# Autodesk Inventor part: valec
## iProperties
Shininess: 64.0
Length Units: 11269
Angle Units: 11279
Time Units: 11290
Mass Units: 11283
Length Display Precision: 3
Angle Display Precision: 2
Compacted: True
Part Number: valec
Document SubType Name: Modeling
Created: 2003-06
Material: Výchozí
Density: 0.0
Volumn: 0.0
Area: 0.0
PropertySet Name: Model Information
Control State: 0
Master: False
Checked Out: False
Title: valec
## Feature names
1. Vysunutí1 [Extrusion]
